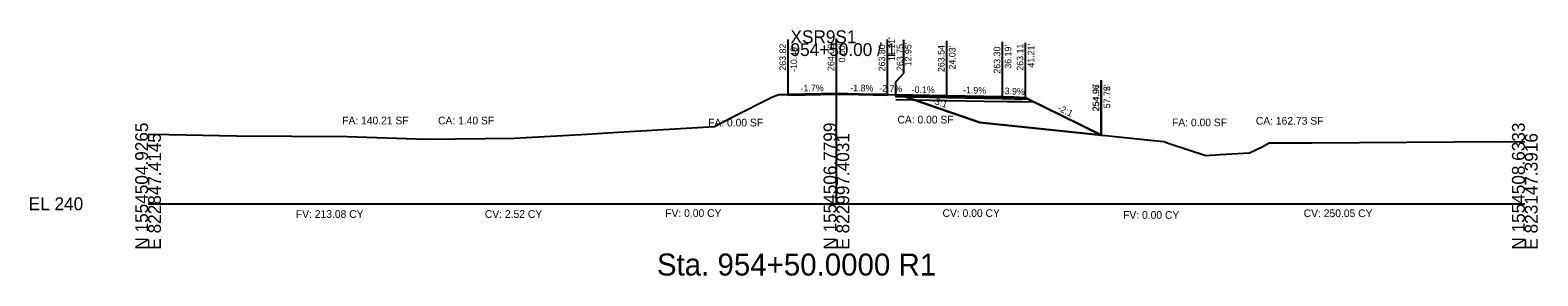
# Model space of a CAD drawing. Extents: x -26 to 823017, y -16 to 1558356.
# Drawn here: x -25.7 to 302.8, y 2484.3 to 2537.8 of the extents above; entities that cross this region are included whole.
import ezdxf

# ---------------------------------------------------------------- set-up
doc = ezdxf.new("R2010")
doc.units = 0
for name, color, linetype in [('ASPHALT_19MM1', 7, 'Continuous'), ('CONST_DCH', 7, 'Continuous'), ('CONST_LV3', 7, 'Continuous'), ('Draft_XS_Grid', 7, 'Continuous'), ('Draft_XS_Text', 7, 'Continuous'), ('DTM_CORRIDOR', 7, 'Continuous'), ('DTM_P_FINISHED_GRADE2', 7, 'Continuous'), ('DTM_TEMP_DROP', 7, 'Continuous'), ('DTM_X_GROUND', 7, 'Continuous'), ('PROFILES_DCH_2', 7, 'Continuous'), ('XS_CELL', 7, 'Continuous'), ('XS_P_ASPHALT', 7, 'Continuous'), ('XS_P_DR_GRAVEL', 7, 'Continuous'), ('XS_P_GROUND', 7, 'Continuous'), ('XS_P_SHOULDER', 7, 'Continuous'), ('XS_P_SUBGRADE_GRANULAR', 7, 'Continuous'), ('XS_P_SUBGRADE_LEVELING', 7, 'Continuous'), ('XS_P_SUBGRADE_MILLING', 7, 'Continuous'), ('XS_P_SUBGRADE_UNDERCUT', 7, 'Continuous'), ('XS_P_TX_CLEARZONE', 7, 'Continuous'), ('XS_P_TX_FS_BS', 7, 'Continuous'), ('XS_SHEET_EW_TX_AREA', 7, 'Continuous'), ('XS_SHEET_EW_TX_VOLUME', 7, 'Continuous')]:
    doc.layers.add(name, color=color, linetype=linetype)

msp = doc.modelspace()

# ---------------------------------------------------------------- linework, layer by layer
at = {"layer": 'ASPHALT_19MM1'}
for points in [[(162.95, 2523.58), (162.95, 2523.37), (174.03, 2523.16), (174.03, 2523.37), (162.95, 2523.58)], [(174.03, 2523.37), (174.03, 2523.16), (186.19, 2522.93), (186.19, 2523.14), (174.03, 2523.37)]]:
    msp.add_lwpolyline(points, dxfattribs=at)
at = {"layer": 'CONST_DCH'}
for points in [[(162.95, 2523.75), (162.95, 2523.58), (174.03, 2523.37), (174.03, 2523.54), (162.95, 2523.75)], [(174.03, 2523.54), (174.03, 2523.37), (186.19, 2523.14), (186.19, 2523.3), (174.03, 2523.54)]]:
    msp.add_lwpolyline(points, dxfattribs=at)
at = {"layer": 'CONST_LV3'}
for points in [[(0, 2515.17), (4.53, 2515.08), (19.29, 2514.84), (43.41, 2514.68), (60.58, 2514.05), (79.83, 2514.31), (82.36, 2514.43), (95.69, 2515.17), (102.41, 2515.58), (123.4, 2516.86), (127.31, 2518.85), (135.91, 2523.22), (136.29, 2523.36), (137.48, 2523.78), (139.51, 2523.82), (139.51, 2523.82)], [(150, 2524), (164, 2523.72)], [(161.11, 2523.8), (161.11, 2523.8), (162.92, 2523.77), (162.92, 2523.76), (162.92, 2523.76), (162.92, 2523.76), (162.92, 2523.76), (162.93, 2523.74), (162.93, 2523.74), (162.93, 2523.74), (162.93, 2523.74), (162.93, 2523.74), (162.93, 2523.74), (162.94, 2523.75), (162.94, 2523.75), (162.94, 2523.75), (162.95, 2523.75), (162.95, 2523.75), (174.03, 2523.54), (174.03, 2523.54), (182.64, 2523.37), (186.19, 2523.3), (188.68, 2523.21), (191.21, 2523.11), (191.22, 2523.1), (195.61, 2520.95), (197.09, 2520.22), (203.11, 2517.24), (206.13, 2515.75), (207.72, 2514.97), (207.74, 2514.96), (207.75, 2514.96), (208.62, 2514.87), (219.01, 2513.78), (221.36, 2513.54), (222.49, 2513.14), (230.52, 2510.51), (233.65, 2510.7), (240, 2511.08), (242.74, 2512.42), (244.31, 2513.25), (253.61, 2513.26), (295.05, 2513.58), (300, 2513.52)], [(163.36, 2523.75), (163.36, 2523.75), (164, 2523.72)], [(191.25, 2523.09), (203.02, 2517.29), (207.72, 2514.97)]]:
    msp.add_lwpolyline(points, dxfattribs=at)
at = {"layer": 'DTM_P_FINISHED_GRADE2'}
msp.add_lwpolyline([(139.51, 2523.82), (150, 2524), (161.11, 2523.8)], dxfattribs=at)
at = {"layer": 'DTM_X_GROUND'}
for points in [[(0, 2515.17), (4.53, 2515.08), (19.29, 2514.84), (43.41, 2514.68), (60.58, 2514.05), (79.83, 2514.31), (82.36, 2514.43), (95.69, 2515.17), (102.41, 2515.58), (123.4, 2516.86), (127.31, 2518.85), (135.91, 2523.22), (136.29, 2523.36), (137.48, 2523.78), (143.14, 2523.88), (150.1, 2524), (154.92, 2523.91), (162.95, 2523.75), (163.99, 2523.54), (165.06, 2523.32), (175.55, 2519.7), (181.22, 2517.74), (208.62, 2514.88), (221.36, 2513.54), (222.49, 2513.14), (230.52, 2510.51), (233.65, 2510.7), (240, 2511.08), (242.74, 2512.42), (244.31, 2513.25), (253.61, 2513.26), (295.05, 2513.58), (300, 2513.52)], [(0, 2515.17), (4.53, 2515.08), (19.29, 2514.84), (43.41, 2514.68), (60.58, 2514.05), (79.83, 2514.31), (82.36, 2514.43), (95.69, 2515.17), (102.41, 2515.58), (123.4, 2516.86), (127.31, 2518.85), (135.91, 2523.22), (136.29, 2523.36), (137.48, 2523.78), (143.14, 2523.88), (150.1, 2524), (154.91, 2523.91), (154.92, 2523.91), (162.92, 2523.77), (162.92, 2523.76), (162.92, 2523.76), (162.92, 2523.76), (162.92, 2523.76), (162.93, 2523.74), (162.93, 2523.74), (162.93, 2523.74), (162.93, 2523.74), (162.93, 2523.74), (162.93, 2523.74), (162.94, 2523.75), (162.94, 2523.75), (162.94, 2523.75), (162.95, 2523.75), (162.95, 2523.75), (174.03, 2523.54), (174.03, 2523.54), (182.64, 2523.37), (186.19, 2523.3), (188.68, 2523.21), (191.21, 2523.11), (191.22, 2523.1), (195.61, 2520.95), (197.09, 2520.22), (203.11, 2517.24), (206.13, 2515.75), (207.72, 2514.97), (207.74, 2514.96), (207.75, 2514.96), (208.62, 2514.87), (219.01, 2513.78), (221.36, 2513.54), (222.49, 2513.14), (230.52, 2510.51), (233.65, 2510.7), (240, 2511.08), (242.74, 2512.42), (244.31, 2513.25), (253.61, 2513.26), (295.05, 2513.58), (300, 2513.52)], [(0, 2515.17), (4.53, 2515.08), (19.29, 2514.84), (43.41, 2514.68), (60.58, 2514.05), (79.83, 2514.31), (82.36, 2514.43), (95.69, 2515.17), (102.41, 2515.58), (123.4, 2516.86), (127.31, 2518.85), (135.91, 2523.22), (136.29, 2523.36), (137.48, 2523.78), (139.51, 2523.82), (139.51, 2523.82), (150, 2524), (150, 2524), (150, 2524), (150, 2524), (150, 2524), (150, 2524), (150, 2524), (150, 2524), (161.11, 2523.8), (161.11, 2523.8), (161.11, 2523.8), (162.92, 2523.77), (162.92, 2523.76), (162.92, 2523.76), (162.92, 2523.76), (162.92, 2523.76), (162.93, 2523.74), (162.93, 2523.74), (162.93, 2523.74), (162.93, 2523.74), (162.93, 2523.74), (162.93, 2523.74), (162.94, 2523.75), (162.94, 2523.75), (162.94, 2523.75), (162.95, 2523.75), (162.95, 2523.75), (174.03, 2523.54), (174.03, 2523.54), (182.64, 2523.37), (186.19, 2523.3), (188.68, 2523.21), (191.21, 2523.11), (191.22, 2523.1), (195.61, 2520.95), (197.09, 2520.22), (203.11, 2517.24), (206.13, 2515.75), (207.72, 2514.97), (207.74, 2514.96), (207.75, 2514.96), (208.62, 2514.87), (219.01, 2513.78), (221.36, 2513.54), (222.49, 2513.14), (230.52, 2510.51), (233.65, 2510.7), (240, 2511.08), (242.74, 2512.42), (244.31, 2513.25), (253.61, 2513.26), (295.05, 2513.58), (300, 2513.52)]]:
    msp.add_lwpolyline(points, dxfattribs=at)
at = {"layer": 'XS_CELL'}
for p, q in [((150, 2500), (150, 2535)), ((0, 2500), (150, 2500)), ((150, 2500), (300, 2500))]:
    msp.add_line(p, q, dxfattribs=at)
at = {"layer": 'XS_P_ASPHALT'}
msp.add_lwpolyline([(139.51, 2523.82), (150, 2524), (150, 2524), (161.11, 2523.8), (161.11, 2523.8), (161.11, 2523.67), (161.11, 2523.67), (150, 2523.88), (150, 2523.88), (139.51, 2523.69), (139.51, 2523.82)], dxfattribs=at)
at = {"layer": 'XS_P_DR_GRAVEL'}
msp.add_lwpolyline([(188.68, 2523.21), (186.19, 2523.3), (186.19, 2523.15), (186.19, 2522.93), (188.92, 2522.88), (191.78, 2522.82), (191.44, 2522.99), (191.21, 2523.11), (188.68, 2523.21)], dxfattribs=at)
at = {"layer": 'XS_P_GROUND'}
for points in [[(163.97, 2523.54), (163.36, 2523.75), (163.36, 2523.75)], [(207.72, 2514.97), (207.72, 2514.97), (181.22, 2517.74), (181.22, 2517.74), (175.55, 2519.7), (175.55, 2519.7), (165.06, 2523.32), (165.06, 2523.32), (165.06, 2523.32), (163.99, 2523.54), (163.97, 2523.54), (163.97, 2523.54)], [(207.72, 2514.97), (207.72, 2514.97), (181.22, 2517.74), (181.22, 2517.74), (175.55, 2519.7), (175.55, 2519.7), (165.06, 2523.32), (165.06, 2523.32), (165.06, 2523.32), (163.99, 2523.54), (163.97, 2523.54), (163.97, 2523.54)], [(191.21, 2523.11), (203.02, 2517.29)], [(203.36, 2517.13), (207.75, 2514.96)]]:
    msp.add_lwpolyline(points, dxfattribs=at)
at = {"layer": 'XS_P_SHOULDER'}
msp.add_lwpolyline([(186.19, 2523.3), (191.21, 2523.11)], dxfattribs=at)
at = {"layer": 'XS_P_SUBGRADE_GRANULAR'}
for points in [[(162.95, 2522.71), (174.03, 2522.49), (186.19, 2522.26)], [(193.21, 2522.12), (190.4, 2522.18), (188.22, 2522.22), (187.1, 2522.25), (186.19, 2522.26)]]:
    msp.add_lwpolyline(points, dxfattribs=at)
at = {"layer": 'XS_P_SUBGRADE_LEVELING'}
for points in [[(161.11, 2523.67), (154.92, 2523.79), (154.92, 2523.79), (154.91, 2523.79), (150.1, 2523.87), (150, 2523.88), (150, 2523.88), (143.14, 2523.76), (143.14, 2523.76), (139.51, 2523.69)], [(139.51, 2523.69), (143.14, 2523.76), (143.14, 2523.76), (150, 2523.88), (150, 2523.88), (150.1, 2523.87), (154.91, 2523.79), (154.92, 2523.79), (154.92, 2523.79), (161.11, 2523.67)]]:
    msp.add_lwpolyline(points, dxfattribs=at)
at = {"layer": 'XS_P_SUBGRADE_MILLING'}
msp.add_lwpolyline([(154.92, 2523.91), (154.91, 2523.91), (150.1, 2524), (150, 2524), (150, 2524), (143.14, 2523.88), (143.14, 2523.88), (139.51, 2523.82), (139.51, 2523.69), (143.14, 2523.76), (143.14, 2523.76), (150, 2523.88), (150, 2523.88), (150.1, 2523.87), (154.91, 2523.79), (154.92, 2523.79), (154.92, 2523.79), (161.11, 2523.67), (161.11, 2523.8), (154.92, 2523.91), (154.92, 2523.91)], dxfattribs=at)
at = {"layer": 'XS_P_SUBGRADE_UNDERCUT'}
msp.add_lwpolyline([(162.95, 2523.75), (165.06, 2523.32), (170.3, 2521.51), (181.22, 2517.74), (194.92, 2516.31), (207.75, 2514.96), (191.22, 2523.1), (186.19, 2523.3), (174.03, 2523.54)], close=True, dxfattribs=at)
at = {"layer": 'XS_P_TX_CLEARZONE'}
for p, q in [((139.51, 2523.82), (139.51, 2535.82)), ((150, 2524), (150, 2536)), ((161.11, 2523.8), (161.11, 2535.8)), ((164.7, 2528.48), (164.7, 2535.75)), ((174.03, 2523.54), (174.03, 2535.54)), ((186.19, 2523.3), (186.19, 2535.3)), ((191.21, 2523.11), (191.21, 2535.11)), ((162.95, 2526.6), (164.7, 2528.48)), ((162.95, 2523.75), (162.95, 2526.6)), ((207.72, 2514.97), (207.72, 2526.97)), ((207.75, 2514.96), (207.75, 2526.96))]:
    msp.add_line(p, q, dxfattribs=at)

# ---------------------------------------------------------------- texts
at = {"layer": 'CONST_DCH'}
for p in [(207.64, 2514.85), (207.67, 2514.84)]:
    msp.add_text('X', height=0.24, dxfattribs=at).set_placement(p)
at = {"layer": 'Draft_XS_Grid'}
msp.add_text('-', height=0.0001, dxfattribs=at).set_placement((0, 2500))
at = {"layer": 'Draft_XS_Text'}
msp.add_text('Sta. 954+50.0000 R1', height=4.8, dxfattribs=at).set_placement((110.88, 2484.35))
at = {"layer": 'DTM_CORRIDOR'}
for p in [(162.87, 2523.63), (173.96, 2523.42), (186.11, 2523.18)]:
    msp.add_text('X', height=0.24, dxfattribs=at).set_placement(p)
at = {"layer": 'DTM_TEMP_DROP'}
for p in [(139.43, 2523.7), (149.92, 2523.88), (161.03, 2523.68)]:
    msp.add_text('X', height=0.24, dxfattribs=at).set_placement(p)
at = {"layer": 'PROFILES_DCH_2'}
for p in [(163.28, 2523.63), (163.89, 2523.42), (207.64, 2514.85)]:
    msp.add_text('X', height=0.24, dxfattribs=at).set_placement(p)
at = {"layer": 'XS_CELL'}
for s, p in [('XSR9S1', (140, 2535)), ('954+50.00 / 1', (140, 2532.2)), ('EL 240', (-26, 2498.6))]:
    msp.add_text(s, height=2.8, dxfattribs=at).set_placement(p)
for s, p in [('N 1554504.9265', (0, 2490)), ('N 1554506.7799', (150, 2490)), ('N 1554508.6333', (300, 2490)), ('E 822847.4145', (2.8, 2490)), ('E 822997.4031', (152.8, 2490)), ('E 823147.3916', (302.8, 2490))]:
    msp.add_text(s, height=2.8, rotation=90, dxfattribs=at).set_placement(p)
at = {"layer": 'XS_P_ASPHALT'}
msp.add_text('X', height=0.24, dxfattribs=at).set_placement((207.67, 2514.84))
at = {"layer": 'XS_P_SHOULDER'}
msp.add_text('X', height=0.24, dxfattribs=at).set_placement((191.13, 2522.99))
at = {"layer": 'XS_P_TX_CLEARZONE'}
for s, p in [('263.82', (139.03, 2529)), ("-10.49'", (141.43, 2528.72)), ('264.00', (149.52, 2528.94)), ("0.00'", (151.92, 2530.79)), ('263.80', (160.63, 2528.85)), ("11.11'", (162.78, 2531.09)), ('263.75', (164.56, 2528.93)), ("12.95'", (166.35, 2529.95)), ('263.54', (173.55, 2528.71)), ("24.03'", (175.95, 2529.26)), ('263.30', (185.71, 2528.36)), ("36.19'", (188.11, 2529.43)), ('263.11', (190.73, 2529.01)), ("41.21'", (193.13, 2529.67)), ('254.97', (207.24, 2520.21)), ('254.96', (207.27, 2520.13)), ("57.72'", (209.64, 2520.8)), ("57.75'", (209.67, 2520.8))]:
    msp.add_text(s, height=1.44, rotation=90, dxfattribs=at).set_placement(p)
at = {"layer": 'XS_P_TX_FS_BS'}
for s, rotation, p in [('-1.7%', 0.9947, (142.19, 2524.46)), ('-1.8%', 358.9622, (153.01, 2524.55)), ('-2.7%', 358.4648, (159.31, 2524.45)), ('-0.1%', 359.9521, (166.39, 2524.14)), ('-1.9%', 358.9103, (177.57, 2524.07)), ('-3.9%', 357.7434, (185.99, 2523.91)), ('-3:1', 341.5651, (170.74, 2521.91)), ('-2:1', 333.761, (198.1, 2520.38))]:
    msp.add_text(s, height=1.44, rotation=rotation, dxfattribs=at).set_placement(p)
at = {"layer": 'XS_SHEET_EW_TX_AREA'}
for s, p in [('FA: 140.21 SF', (42.29, 2517.3)), ('CA: 1.40 SF', (63.19, 2517.3)), ('FA: 0.00 SF', (122.03, 2516.85)), ('CA: 0.00 SF', (163.29, 2517.5)), ('FA: 0.00 SF', (223.12, 2516.88)), ('CA: 162.73 SF', (241.39, 2517.24))]:
    msp.add_text(s, height=1.68, dxfattribs=at).set_placement(p)
at = {"layer": 'XS_SHEET_EW_TX_VOLUME'}
for s, p in [('FV: 213.08 CY', (32.21, 2496.92)), ('CV: 2.52 CY', (73.39, 2496.92)), ('FV: 0.00 CY', (112.7, 2497.12)), ('CV: 0.00 CY', (173.12, 2497.12)), ('FV: 0.00 CY', (212.47, 2496.72)), ('CV: 250.05 CY', (251.82, 2497.09))]:
    msp.add_text(s, height=1.68, dxfattribs=at).set_placement(p)

doc.saveas('drawing.dxf')
